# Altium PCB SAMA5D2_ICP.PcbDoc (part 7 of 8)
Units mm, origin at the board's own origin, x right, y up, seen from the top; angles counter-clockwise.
Board outline 150 x 100 mm, 6 copper layers (L1 - TOP, L2 - GND, L3 - SIG, L4 - SIG, L5 - VCC, L6 - BOT), stack 1.512 mm thick; 708 components, 597 nets, 2710 pads, 1437 vias.
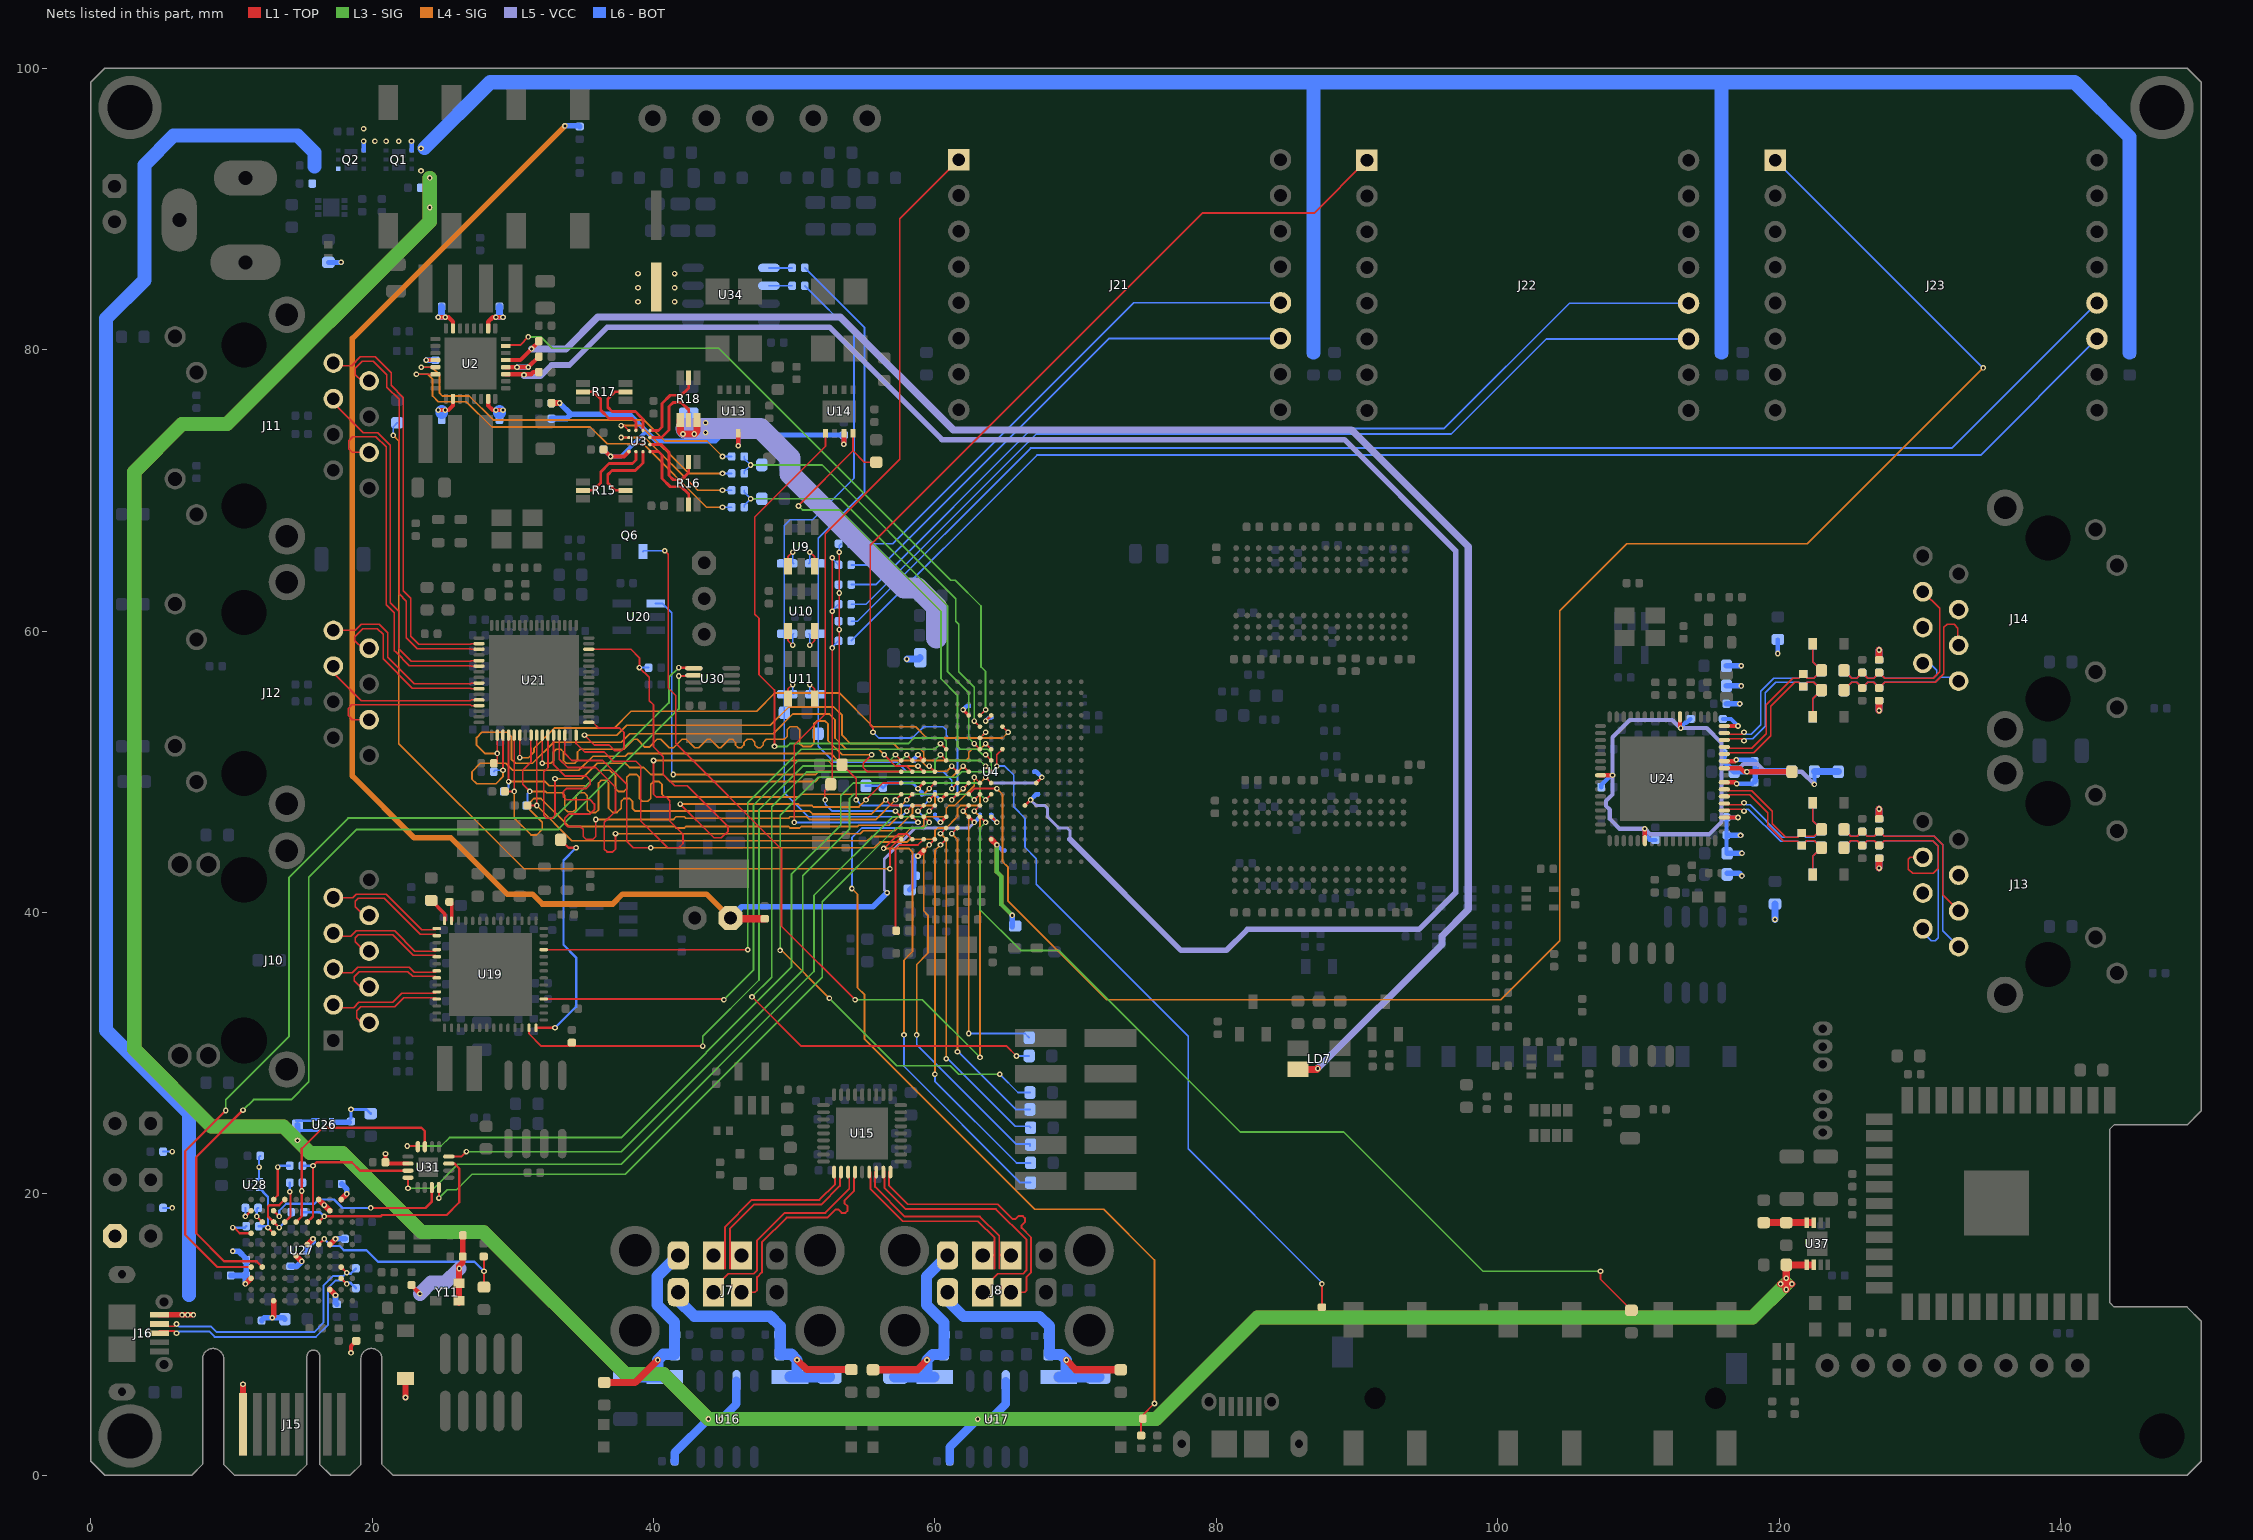
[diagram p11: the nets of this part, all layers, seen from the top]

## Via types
v1: diameter 0.4, hole 0.2, L1 - TOP to L6 - BOT, tented both sides, 1312 vias
v2: diameter 0.55, hole 0.3, L1 - TOP to L6 - BOT, 84 vias
v3: diameter 0.4, hole 0.2, L1 - TOP to L6 - BOT, tented top, 25 vias
v4: diameter 0.55, hole 0.3, L1 - TOP to L6 - BOT, tented bottom, 16 vias

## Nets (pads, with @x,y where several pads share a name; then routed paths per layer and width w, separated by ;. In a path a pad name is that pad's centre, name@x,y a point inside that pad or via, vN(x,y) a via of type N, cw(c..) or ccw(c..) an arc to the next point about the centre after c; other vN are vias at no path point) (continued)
PC22: R131.1 U4.H2 U19.27 | length 44.3
  L1 - TOP w0.125: U19.27@31.15,31.8 31.15,31.381 32.031,30.5 v1(43.5,30.5) ; v1(58,51.2) U4.H2@58.4,50.8
  L3 - SIG w0.125: v1(43.5,30.5) 43.5,31.2 47.5,35.2 47.5,47.3 50.6,50.4 57.2,50.4 v1(58,51.2)
PC23: U4.G5 U19.39 | length 41
  L1 - TOP w0.125: U19.39@32.2,37.35 v1(46.7,37.35) ; v1(60.4,52) U4.G5@60.8,51.6
  L3 - SIG w0.125: v1(46.7,37.35) 46.7,47.8 50.5,51.6 60,51.6 v1(60.4,52)
PC24: U4.H1 U19.32 | length 39.6
  L1 - TOP w0.125: U19.32@32.2,33.85 44.95,33.85 v1(45,33.8) ; v1(57.2,51.2) U4.H1@57.6,50.8
  L3 - SIG w0.125: v1(45,33.8) 47.1,35.9 47.1,47.6 50.3,50.8 56.8,50.8 v1(57.2,51.2)
PC25: R235.1 U4.H5 | length 50
  L1 - TOP w0.125: v1(47,34) 50.5,30.5 65.1,30.5 v1(65.8,29.8) ; v1(60.4,51.2) U4.H5@60.8,50.8
  L3 - SIG w0.125: v1(47,34) 48.4,35.4 48.4,47.5 50.875,49.975 59.775,49.975 60,50.2 60,50.8 v1(60.4,51.2)
  L6 - BOT w0.125: v1(65.8,29.8) R235.1@66.7,29.8
PC26: U4.J9 U14.1 | length 42.2
  L1 - TOP w0.125: v1(48.6,51.8) 48.6,55.8 47.5,56.9 47.5,60.9 47.2,61.2 47.2,68.1 52.225,73.125 U14.1@52.225,74.05 ; v1(63.6,50.4) U4.J9@64,50
  L3 - SIG w0.125: v1(48.6,51.8) 49.5,51.8 49.7,52 58.1,52 58.5,52.4 60.575,52.4 60.8,52.175 60.8,51.075 60.775,51.05 61.025,50.8 63.2,50.8 v1(63.6,50.4)
PC27: C125.2 U4.H9 U14.4 | length 34.9
  L1 - TOP w0.125: v1@50.28,68.905 54.175,72.8 ; U14.4@54.175,74.05 54.175,72.8 ; C125.2@55.831,71.994 54.981,71.994 54.175,72.8 ; v1(63.6,51.2) U4.H9@64,50.8
  L3 - SIG w0.125: v1(50.3,68.885) 50.309,68.885 50.594,68.6 53.231,68.6 60.435,61.396 60.435,56.6 61.6,55.435 61.6,51.8 61.8,51.6 63,51.6 63.4,51.2 v1(63.6,51.2)
PC28: R47.1 R60.1 R61.1 U4.E8 | length 30.7
  L1 - TOP w0.125: v1(62.8,53.6) U4.E8@63.2,53.2
  L3 - SIG w0.125: v1(46.9,71.8) 51.98,71.8 61.478,62.302 61.478,60.694 61.7,60.472 61.7,57.1 62.8,56 v1(62.8,53.6)
  L6 - BOT w0.125: R61.1@46.45,71.2 46.45,71.35 v1(46.9,71.8) ; R60.1@46.45,72.4 46.45,72.25 v1(46.9,71.8) ; R47.1@47.7,71.8 v1(46.9,71.8)
PC28_MCP16502: R60.2 U2.5 | length 26.4
  L1 - TOP w0.125: v1(23.5,78.75) U2.5@24.5,78.75
  L4 - SIG w0.125: v1(23.5,78.75) 24.25,78.75 24.8,78.2 24.8,76.9 25,76.7 26.9,76.7 28.6,75 39.3,75 40.8,73.5 43.8,73.5 v1(44.9,72.4)
  L6 - BOT w0.125: v1(44.9,72.4) R60.2@45.55,72.4
PC28_PAC1934: R61.2 U3.D4 | length 10
  L1 - TOP w0.125: v1(37.7,74.6) 37.9,74.6 U3.D4@38.25,74.25
  L4 - SIG w0.125: v1(37.7,74.6) 39.1,74.6 42.5,71.2 v1(44.9,71.2)
  L6 - BOT w0.125: v1(44.9,71.2) R61.2@45.55,71.2
PC29: R44.1 R62.1 R63.1 U4.G8 | length 30.7
  L1 - TOP w0.125: v1(62.8,52) U4.G8@63.2,51.6
  L3 - SIG w0.125: v1(46.9,69.4) 53.28,69.4 60.9,61.78 60.9,57.1 62.4,55.6 62.4,52.4 v1(62.8,52)
  L6 - BOT w0.125: R62.1@46.45,68.8 46.45,68.95 v1(46.9,69.4) ; R63.1@46.45,70 46.45,69.85 v1(46.9,69.4) ; R44.1@47.7,69.4 v1(46.9,69.4)
PC29_MCP16502: R62.2 U2.6 | length 28.4
  L1 - TOP w0.125: v1(23.15,78.25) U2.6@24.5,78.25
  L4 - SIG w0.125: v1(23.15,78.25) 23.95,78.25 24.3,77.9 24.3,76.7 24.7,76.3 26.7,76.3 28.5,74.5 35.5,74.5 36.7,73.3 39.266,73.3 43.766,68.8 v1(44.9,68.8)
  L6 - BOT w0.125: v1(44.9,68.8) R62.2@45.55,68.8
PC29_PAC1934: R63.2 U3.C4 | length 10
  L1 - TOP w0.125: v1(37.7,73.75) U3.C4@38.25,73.75
  L4 - SIG w0.125: v1(37.7,73.75) 39.381,73.75 43.131,70 v1(44.9,70)
  L6 - BOT w0.125: v1(44.9,70) R63.2@45.55,70
PC30: R234.2 U4.F8 | length 51.8
  L1 - TOP w0.125: U4.F8@63.2,52.4 v1(63.6,52.8)
  L3 - SIG w0.125: v1(49,37.3) 49,46.9 51.7,49.6 61.5,49.6 61.9,50 63.8,50 64,50.2 64,51.35 63.75,51.6 63.4,51.6 63.2,51.8 63.2,52.4 v1(63.6,52.8) ; v1(52.5,33.9) 57.3,29.1 61.1,29.1 61.7,28.5 v1(64.6,28.5)
  L4 - SIG w0.125: v1(49,37.3) 49.1,37.3 v1(52.5,33.9)
  L6 - BOT w0.125: v1(64.6,28.5) 65.9,27.2 R234.2@66.75,27.2
PC31: U2.23 U4.D8 | length 50
  L1 - TOP w0.125: U2.23@29.5,80.25 29.567,80.317 30.517,80.317 v1(31.1,80.9) ; U4.D8@63.2,54 v1(63.6,54.4)
  L3 - SIG w0.125: v1(31.1,80.9) 32,80.9 32.8,80.1 44.625,80.1 61.113,63.612 61.438,63.612 63.275,61.775 63.275,57.45 63.6,57.125 v1(63.6,54.4)
PD0: R254.1 U4.G10 | length 49.7
  L1 - TOP w0.125: v1(64.4,50.4) 64.4,51.2 U4.G10@64.8,51.6 ; R254.1@87.5,11.95 v1(87.5,13.6)
  L6 - BOT w0.125: v1(64.4,50.4) 64.966,50.4 65.6,49.766 65.6,47.5 66.4,46.7 66.4,44.625 67.2,43.825 67.2,42 78,31.2 78,23.2 87.5,13.7 v1(87.5,13.6)
PD1: U4.E10 U21.22 | length 40.4
  L1 - TOP w0.125: v1(30.5,51) U21.22@30.5,52.6 ; U4.E10@64.8,53.2 v1(65.2,52.8)
  L4 - SIG w0.125: v1(30.5,51) 31.117,51 31.5,51.383 31.5,51.65 32.95,53.1 37.2,53.1 38.4,54.3 47.334,54.3 48.634,55.6 53.2,55.6 55.6,53.2 58.625,53.2 59.425,52.4 64.8,52.4 v1(65.2,52.8)
PD2: U4.G9 U21.33 | length 40.4
  L1 - TOP w0.125: v1(35.1,52.6) 35.8,51.9 36.85,51.9 37.25,51.5 37.7,51.5 37.9,51.7 37.9,52.8 37.6,53.1 36.1,53.1 35.7,53.5 U21.33@35.4,53.5 ; v1(63.6,52) U4.G9@64,51.6
  L4 - SIG w0.125: v1(35.1,52.6) 37.4,52.6 38.1,53.3 48.3,53.3 49.6,54.6 52.8,54.6 53.4,54 53.4,52.6 54,52 57.075,52 57.475,51.6 58.975,51.6 59.2,51.375 59.2,51.025 59.425,50.8 62.2,50.8 62.4,51 62.4,51.375 62.625,51.6 63.2,51.6 v1(63.6,52)
PD3: R177.1 U4.K1 U21.46 | length 41
  L1 - TOP w0.125: U21.46@35.4,58.7 38.4,58.7 39,58.1 v1(39,57.4) 39.7,56.7 39.7,55.048 40,54.748 40,51.775 40.7,51.075 40.7,49.8 41.5,49 42.4,49 45.3,46.1 45.3,45.775 44.825,45.3 44.3,45.3 v1(41.9,47.7) ; v1(55.1,48) 56.3,49.2 U4.K1@57.6,49.2
  L4 - SIG w0.125: v1(41.9,47.7) 50.3,47.7 50.4,47.6 51.266,47.6 51.366,47.5 54.6,47.5 v1(55.1,48)
  L6 - BOT w0.125: v1(39,57.4) R177.1@39.65,57.4
PD4: U4.J6 U20.1 | length 33.6
  L1 - TOP w0.125: v1(61.2,50.4) U4.J6@61.6,50
  L4 - SIG w0.125: v1(41.4,49.8) 51.52,49.8 51.75,50.03 60.83,50.03 v1(61.2,50.4)
  L6 - BOT w0.125: U20.1@40.15,61.95 40.65,61.95 41.3,61.3 41.3,49.9 v1(41.4,49.8)
PD5: R157.1 U4.J4 U21.19 | length 41.1
  L1 - TOP w0.125: v1(29.3,50.1) U21.19@29.3,52.6 ; v1(59.6,50.4) U4.J4@60,50
  L4 - SIG w0.125: v1(29.3,50.1) 29.3,49.64 28.81,49.15 27.425,49.15 27.1,49.475 27.1,50 27.7,50.6 29.5,50.6 30,50.1 34.7,50.1 35.7,51.1 38,51.1 38.2,51.3 52.6,51.3 53.1,50.8 59,50.8 59.4,50.4 v1(59.6,50.4)
  L6 - BOT w0.125: R157.1@28.65,50 28.75,50.1 v1(29.3,50.1)
PD6: R266.1 U4.J2 U21.18 | length 41.2
  L1 - TOP w0.125: R266.1@28.9,50.6 v1(28.9,51.3) U21.18@28.9,52.6 ; v1(56.4,51.2) 57.2,50.4 58,50.4 U4.J2@58.4,50
  L4 - SIG w0.125: v1(28.9,51.3) 28,51.3 27.425,51.875 27.425,52.425 27.8,52.8 29.6,52.8 29.9,52.5 29.9,50.9 30.2,50.6 31.4,50.6 32.9,52.1 37.7,52.1 38.3,52.7 48.5,52.7 49.9,54.1 52.5,54.1 52.9,53.7 52.9,52.4 53.7,51.6 56,51.6 v1(56.4,51.2)
PD7: U4.J7 U21.27 | length 40.4
  L1 - TOP w0.125: U21.27@32.5,52.6 32.5,50.3 32.2,50 32.2,46.9 32.4,46.7 32.8,46.7 33,46.9 v1(33,49.5) ; v1(62,50.4) U4.J7@62.4,50
  L4 - SIG w0.125: v1(33,49.5) 34.9,49.5 36,50.6 38,50.6 38.3,50.3 39.3,50.3 39.8,49.8 40.7,49.8 41.2,49.3 51.5,49.3 51.8,49.6 61.2,49.6 v1(62,50.4)
PD8: U4.J1 U21.26 | length 40.4
  L1 - TOP w0.125: v1(32.1,50.6) U21.26@32.1,52.6 ; v1(55.5,51.2) 54.9,50.6 54.9,50.3 55.2,50 U4.J1@57.6,50
  L4 - SIG w0.125: v1(32.1,50.6) 32.7,50.6 32.9,50.8 32.9,51.4 33.1,51.6 33.4,51.6 33.6,51.4 33.6,50.8 33.8,50.6 34.4,50.6 34.6,50.8 34.6,51.4 34.8,51.6 37.9,51.6 38.6,52.3 38.834,52.3 39.384,51.75 39.7,51.75 40.25,52.3 40.525,52.3 41.125,51.7 41.425,51.7 42.025,52.3 42.325,52.3 42.925,51.7 43.225,51.7 43.825,52.3 44.025,52.3 44.625,51.7 44.78,51.7 45.38,52.3 45.625,52.3 45.825,52.1 45.825,51.9 46.025,51.7 46.225,51.7 46.425,51.9 46.425,52.075 46.65,52.3 47,52.3 47.2,52.1 47.2,51.9 47.4,51.7 47.6,51.7 47.8,51.9 47.8,52.075 48.025,52.3 49.3,52.3 49.5,52.5 49.5,53 49.7,53.2 50.2,53.2 50.4,53 50.4,52 50.6,51.8 51.2,51.8 51.4,52 51.4,53.4 51.6,53.6 52.2,53.6 52.4,53.4 52.4,52.2 53.4,51.2 v1(55.5,51.2)
PD9: U4.K9 U21.30 | length 40.4
  L1 - TOP w0.125: U21.30@33.7,52.6 33.7,51.3 34.2,50.8 36.4,50.8 38.1,49.1 38.1,45.05 38.55,44.6 v1(39.8,44.6) ; v1(63.6,49.6) U4.K9@64,49.2
  L4 - SIG w0.125: v1(39.8,44.6) 55.7,44.6 56.1,45 58,45 58.2,45.2 59.8,45.2 60,45.4 60,45.8 60.2,46 60.8,46 61.6,46.8 61.6,47.376 61.824,47.6 63.1,47.6 63.2,47.7 63.2,49.2 v1(63.6,49.6)
PD10: U4.J3 U21.32 | length 40.4
  L1 - TOP w0.125: U21.32@34.5,52.6 34.5,52.007 35.107,51.4 36.5,51.4 37.15,50.75 38.757,50.75 39.1,50.407 39.1,46.5 41,44.6 41.8,44.6 42.1,44.9 42.1,45.56 41.16,46.5 41.16,47.94 40.9,48.2 40.2,48.2 40,48.4 v1(40,50.8) ; v1(58.8,50.4) U4.J3@59.2,50
  L4 - SIG w0.125: v1(40,50.8) 52.4,50.8 52.8,50.4 v1(58.8,50.4)
PD11: R259.1 U4.M1 U21.24 | length 41.5
  L1 - TOP w0.125: v1(31.2,48.6) 30.7,49.1 30.7,50.1 31.3,50.7 31.3,51.666 31.275,51.691 31.275,52.575 U21.24@31.3,52.6 ; v1(56.5,48) 56.9,47.6 U4.M1@57.6,47.6
  L4 - SIG w0.125: v1(31.2,48.6) 32.3,48.6 32.4,48.5 33.5,48.5 33.7,48.3 33.7,47.35 33.9,47.15 34.3,47.15 34.5,47.35 34.5,48.3 34.7,48.5 35.1,48.5 35.3,48.3 35.3,47.3 35.5,47.1 35.9,47.1 36.1,47.3 36.1,49.2 36.3,49.4 36.6,49.4 36.8,49.2 36.8,47.4 37.1,47.1 37.4,47.1 37.7,47.4 37.7,47.9 37.9,48.1 38.3,48.1 38.5,47.9 38.5,47.4 38.7,47.2 51.1,47.2 51.3,47 55.5,47 v1(56.5,48)
  L6 - BOT w0.125: R259.1@31.05,47.6 31.05,48.45 v1(31.2,48.6)
PD12: R267.1 U4.K8 U21.25 | length 41
  L1 - TOP w0.125: R267.1@31.1,47.6 v1(31.7,47.6) U21.25@31.7,52.6 ; v1(62.8,49.6) U4.K8@63.2,49.2
  L4 - SIG w0.125: v1(31.7,47.6) 34.2,45.1 55.2,45.1 55.5,45.4 57.7,45.4 58.3,46 59,46 59.2,46.2 59.2,46.6 59.4,46.8 60.7,46.8 60.8,46.9 60.8,47.4 61,47.6 61.4,47.6 62.8,49 v1(62.8,49.6)
PD13: R155.1 U4.L2 U21.21 | length 41.1
  L1 - TOP w0.125: R155.1@29.45,48.6 v1(30.1,48.6) U21.21@30.1,52.6 ; v1(58,48) U4.L2@58.4,48.4
  L4 - SIG w0.125: v1(30.1,48.6) 30.1,46.7 31.3,45.5 31.7,45.5 32.1,45.9 32.1,46.4 31.2,47.3 31.2,47.8 31.5,48.1 32,48.1 34,46.1 41.5,46.1 41.6,46 42.2,46 42.3,46.1 49.6,46.1 49.7,46 50.4,46 50.5,46.1 54.5,46.1 54.6,46.2 56.766,46.2 57.6,47.034 57.6,47.6 v1(58,48)
PD14: R156.2 U4.K4 U21.20 | length 41.2
  L1 - TOP w0.125: v1(29.7,49.3) U21.20@29.7,52.6 ; v1(59.6,48.8) U4.K4@60,49.2
  L4 - SIG w0.125: v1(29.7,49.3) 32.3,49.3 32.6,49 35.2,49 36.3,50.1 36.9,50.1 37.3,49.7 37.3,48.8 37.5,48.6 37.9,48.6 38.1,48.8 38.1,49.6 38.3,49.8 38.8,49.8 39,49.6 39,48.1 39.2,47.9 39.6,47.9 39.8,48.1 39.8,49.1 40,49.3 40.4,49.3 40.6,49.1 40.6,48.4 40.8,48.2 50.3,48.2 50.5,48.4 59.2,48.4 v1(59.6,48.8)
  L6 - BOT w0.125: R156.2@29.45,48.6 29.7,48.85 v1(29.7,49.3)
PD15: U4.K7 U21.29 | length 40.4
  L1 - TOP w0.125: U21.29@33.3,52.6 33.3,50.9 33.9,50.3 35.9,50.3 37.3,48.9 37.3,47.2 36.5,46.4 36.5,44.5 36.7,44.3 37.1,44.3 37.3,44.5 v1(37.3,45.6) ; v1(62,48.8) U4.K7@62.4,49.2
  L4 - SIG w0.125: v1(37.3,45.6) 54.7,45.6 54.9,45.8 57.166,45.8 58.4,47.034 58.4,47.4 58.6,47.6 59.9,47.6 60,47.7 60,48.2 60.2,48.4 61.6,48.4 v1(62,48.8)
PD16: U4.L1 U21.28 | length 40.4
  L1 - TOP w0.125: U21.28@32.9,52.6 32.9,50.5 33.7,49.7 35.2,49.7 35.5,49.4 35.5,49.1 35.2,48.8 33.8,48.8 33.6,48.6 33.6,48.2 33.8,48 35.5,48 35.8,47.7 35.8,47.3 35.5,47 34,47 33.7,46.7 33.7,46.3 33.9,46.1 34.8,46.1 35,45.9 35,45.4 35.2,45.2 35.7,45.2 35.9,45.4 v1(35.9,46.6) ; v1(57.2,48) U4.L1@57.6,48.4
  L4 - SIG w0.125: v1(35.9,46.6) 41.4,46.6 41.6,46.8 42.2,46.8 42.3,46.7 49.6,46.7 49.7,46.8 50.9,46.8 51.1,46.6 55.8,46.6 v1(57.2,48)
PD19: R45.1 R48.1 R49.1 R50.1 R269.1 U4.K6 | length 48.8
  L1 - TOP w0.125: v1(61.2,48.8) U4.K6@61.6,49.2
  L6 - BOT w0.125: R269.1@50.75,85.805 55,81.555 55,69.9 51.7,66.6 R45.1@51.7,52.7 51.7,51.8 52.8,50.7 57.3,50.7 58,50 60.6,50 61.2,49.4 v1(61.2,48.8)
PD19_ECC608: R269.2 U34.5 | length 1.7
  L6 - BOT w0.125: U34.5@48.2,85.805 R269.2@49.85,85.805
PD19_EEPROM1: R48.2 U9.3 | length 2
  L1 - TOP w0.125: v1(51.1,65.6) 51.125,65.6 51.45,65.275 U9.3@51.45,64.6
  L6 - BOT w0.125: R48.2@51.05,64.8 51.1,64.85 v1(51.1,65.6)
PD19_EEPROM2: R49.2 U10.3 | length 2
  L1 - TOP w0.125: v1(51.1,59) 51.125,59 51.45,59.325 U10.3@51.45,60
  L6 - BOT w0.125: R49.2@51.05,59.8 51.1,59.75 v1(51.1,59)
PD19_EEPROM3: R50.2 U11.3 | length 1.9
  L1 - TOP w0.125: v1(51.1,56.2) 51.125,56.2 51.45,55.875 U11.3@51.45,55.2
  L6 - BOT w0.125: R50.2@51.05,55.5 51.1,55.55 v1(51.1,56.2)
PD20: R42.1 R51.1 R52.1 R53.1 R270.1 U4.M2 | length 50.6
  L1 - TOP w0.125: v1(58,47.2) U4.M2@58.4,47.6
  L6 - BOT w0.125: R270.1@50.75,84.535 54.25,81.035 54.25,70.85 51.3,67.9 49.7,67.9 49.3,67.5 49.3,48.5 51,46.8 57.6,46.8 v1(58,47.2)
PD20_ECC608: R270.2 U34.6 | length 1.7
  L6 - BOT w0.125: U34.6@48.2,84.535 R270.2@49.85,84.535
PD20_EEPROM1: R51.2 U9.1 | length 2
  L1 - TOP w0.125: U9.1@49.55,64.6 49.55,65.275 49.875,65.6 v1(49.9,65.6)
  L6 - BOT w0.125: v1(49.9,65.6) 49.9,64.85 R51.2@49.95,64.8
PD20_EEPROM2: R52.2 U10.1 | length 2
  L1 - TOP w0.125: U10.1@49.55,60 49.55,59.325 49.875,59 v1(49.9,59)
  L6 - BOT w0.125: v1(49.9,59) 49.9,59.75 R52.2@49.95,59.8
PD20_EEPROM3: R53.2 U11.1 | length 1.9
  L1 - TOP w0.125: U11.1@49.55,55.2 49.55,55.875 49.875,56.2 v1(49.9,56.2)
  L6 - BOT w0.125: v1(49.9,56.2) 49.9,55.55 R53.2@49.95,55.5
PD21: R46.1 R54.1 R55.1 R56.1 U4.N1 | length 25.6
  L1 - TOP w0.125: v1(52.2,48) 52.165,48.035 52.165,48.665 R46.1@52.6,49.1 52.7,49.2 v1(52.7,58.8) v1(52.7,61.4) v1(52.7,65.2) ; v1(57.2,47.2) U4.N1@57.6,46.8
  L6 - BOT w0.125: v1(52.2,48) 52.2,47.7 52.7,47.2 v1(57.2,47.2) ; v1(52.7,58.8) 52.7,58.85 R56.1@53.15,59.3 ; v1(52.7,61.4) 52.7,61.45 R55.1@53.15,61.9 ; v1(52.7,65.2) 52.7,65.15 R54.1@53.15,64.7
PD21_MKBUS1: J21.11 R54.2 | length 37.2
  L6 - BOT w0.125: R54.2@54.05,64.7 56.3,64.7 72.395,80.795 J21.11@84.56,80.795
PD21_MKBUS2: J22.11 R55.2 | length 67.3
  L6 - BOT w0.125: R55.2@54.05,61.9 55.1,61.9 67.2,74 96.7,74 103.455,80.755 J22.11@113.56,80.755
PD21_MKBUS3: J23.11 R56.2 | length 97.4
  L6 - BOT w0.125: R56.2@54.05,59.3 67.25,72.5 134.315,72.5 J23.11@142.58,80.765
PD22: R43.1 R57.1 R58.1 R59.1 U4.L4 | length 26.1
  L1 - TOP w0.125: v1(53.2,65.6) v1(53.2,62.7) v1(53.2,60.1) 53.2,50.7 R43.1@53.4,50.5 54.4,49.5 v1(54.4,48) ; v1(59.6,48) U4.L4@60,48.4
  L6 - BOT w0.125: R59.1@53.15,60.7 53.2,60.65 v1(53.2,60.1) ; R58.1@53.15,63.3 53.2,63.25 v1(53.2,62.7) ; v1(53.2,65.6) 53.2,66.05 R57.1@53.35,66.2 ; v1(54.4,48) 54.8,47.6 59.2,47.6 v1(59.6,48)
PD22_MKBUS1: J21.12 R57.2 | length 37.6
  L6 - BOT w0.125: R57.2@54.05,66.2 57,66.2 74.135,83.335 J21.12@84.56,83.335
PD22_MKBUS2: J22.12 R58.2 | length 67.8
  L6 - BOT w0.125: R58.2@54.05,63.3 55.8,63.3 66.9,74.4 96.2,74.4 105.095,83.295 J22.12@113.56,83.295
PD22_MKBUS3: J23.12 R59.2 | length 97.9
  L6 - BOT w0.125: R59.2@54.05,60.7 54.5,60.7 66.8,73 132.275,73 J23.12@142.58,83.305
PD23: R129.2 R130.1 U4.M3 | length 61.8
  L1 - TOP w0.125: v1(58.8,47.2) U4.M3@59.2,47.6 ; R129.2@74.652,2.824 74.652,3.899 R130.1@74.777,4.024 74.777,4.277 v1(75.6,5.1)
  L4 - SIG w0.125: v1(54.1,41.7) 54.5,41.3 54.5,34.64 55,34.14 55,31 67.1,18.9 72,18.9 75.6,15.3 v1(75.6,5.1)
  L6 - BOT w0.125: v1(54.1,41.7) 54.1,45.3 54.8,46 59,46 59.2,46.2 59.2,46.8 v1(58.8,47.2)
PD24: J23.1 U4.L7 | length 136
  L1 - TOP w0.125: U4.L7@62.4,48.4 62.8,48.8 v1(64.4,48.8)
  L4 - SIG w0.125: v1(64.4,48.8) 64.8,48.4 64.8,43.6 65.202,43.198 65.202,40.798 72.2,33.8 100.2,33.8 104.4,38 104.4,61.434 104.966,62 109.166,66.2 119.6,66.2 122,66.2 v1(134.5,78.7)
  L6 - BOT w0.125: J23.1@119.72,93.465 v1@134.542,78.643
PD25: J22.1 U4.L6 | length 72.1
  L1 - TOP w0.125: v1(55.6,52.8) 55.6,53.1 55.4,53.3 55.4,66.1 79,89.7 86.945,89.7 J22.1@90.7,93.455 ; v1(61.2,48) U4.L6@61.6,48.4
  L6 - BOT w0.125: v1(55.6,52.8) 56,52.4 58.4,52.4 59.2,53.2 60.576,53.2 60.8,52.976 60.8,52.6 61,52.4 61.4,52.4 61.6,52.2 61.6,48.4 v1(61.2,48)
PD26: J21.1 U4.N2 | length 61.3
  L1 - TOP w0.125: v1(50,46.4) 50,51.9 52.2,54.1 52.2,66.9 57.5,72.2 57.5,89.295 J21.1@61.7,93.495 ; U4.N2@58.4,46.8 v1(58.8,46.4)
  L6 - BOT w0.125: v1(50,46.4) v1(58.8,46.4)
PD27: U4.L8 U31.8 | length 53.9
  L1 - TOP w0.125: U31.8@25.45,22.65 26.35,22.65 v1(26.7,23) ; v1(62.8,48) U4.L8@63.2,48.4
  L3 - SIG w0.125: v1(26.7,23) 37.7,23 50.6,35.9 50.6,42.6 53.934,45.934 53.934,48.1 54.234,48.4 62.4,48.4 v1(62.8,48)
PD28: U4.M4 U31.16 | length 52.6
  L1 - TOP w0.125: v1(22.55,20.4) U31.16@22.55,21.15 ; v1(59.6,47.2) U4.M4@60,47.6
  L3 - SIG w0.125: v1(22.55,20.4) 24.4,20.4 26.1,22.1 37.7,22.1 51.4,35.8 51.4,41.2 57,46.8 59.2,46.8 v1(59.6,47.2)
PD29: U4.N3 U31.4 | length 50.4
  L1 - TOP w0.125: v1(24.75,19.7) U31.4@24.75,20.45 ; U4.N3@59.2,46.8 v1(59.6,46.4)
  L3 - SIG w0.125: v1(24.75,19.7) 25.35,20.3 26,20.3 27.1,21.4 38,21.4 52,35.4 52,40.766 57.234,46 59.2,46 v1(59.6,46.4)
PD30: U4.L9 U31.12 | length 59.1
  L1 - TOP w0.125: v1(22.5,23.4) 23.2,23.4 U31.12@23.25,23.35 ; v1(63.6,48) U4.L9@64,48.4
  L3 - SIG w0.125: v1(22.5,23.4) 24.9,23.4 25.5,24 37.7,24 49.8,36.1 49.8,42.7 53.3,46.2 53.3,48.3 54.2,49.2 63,49.2 63.2,49 63.2,48.4 v1(63.6,48)
PD31: R228.2 U4.M7 | length 21
  L1 - TOP w0.125: v1(62,47.2) U4.M7@62.4,47.6
  L4 - SIG w0.125: v1(62,47.2) 62.4,46.8 v1(62.4,31.4)
  L6 - BOT w0.125: v1(62.4,31.4) 66.4,31.4 R228.2@66.7,31.1
PIOBU1: R255.2 U4.N8 | length 65.4
  L1 - TOP w0.125: U4.N8@63.2,46.8 v1(63.6,46.4) ; v1(107.3,14.5) 107.3,13.925 R255.2@109.5,11.725
  L3 - SIG w0.125: v1(63.6,46.4) 63.2,46 63.2,40.2 66.1,37.3 68.8,37.3 81.7,24.4 89.05,24.4 98.95,14.5 v1(107.3,14.5)
PIOBU2: R224.1 U4.R2 | length 32.7
  L1 - TOP w0.125: v1(56.35,44.55) 56.385,44.55 57.4,45.565 58.035,45.565 U4.R2@58.4,45.2
  L4 - SIG w0.125: v1(56.35,44.55) 58.15,44.55 58.4,44.3 58.4,37.2 57.8,36.6 v1(57.8,31.3)
  L6 - BOT w0.125: v1(57.8,31.3) 57.8,29.068 66.068,20.8 R224.1@66.8,20.8
PIOBU3: R232.2 U4.R5 | length 26.7
  L1 - TOP w0.125: v1(60.4,44.8) U4.R5@60.8,45.2
  L4 - SIG w0.125: v1(60,28.5) 60,44.4 v1(60.4,44.8)
  L6 - BOT w0.125: v1(60,28.5) 60,28 65.8,22.2 R232.2@66.8,22.2
PIOBU4: R225.1 U4.R4 | length 26.5
  L1 - TOP w0.125: v1(59.6,44.8) U4.R4@60,45.2
  L4 - SIG w0.125: v1(58.7,31.3) 58.7,36.3 59.5,37.1 59.5,39.8 59.2,40.1 59.2,44.4 v1(59.6,44.8)
  L6 - BOT w0.125: v1(58.7,31.3) 58.7,30.6 65.75,23.55 66.75,23.55 R225.1@66.75,23.4
PIOBU5: R233.2 U4.P5 | length 24.8
  L1 - TOP w0.125: v1(60.4,45.6) U4.P5@60.8,46
  L4 - SIG w0.125: v1(60.4,45.6) 60.8,45.2 v1(60.8,29.6)
  L6 - BOT w0.125: v1(60.8,29.6) 60.9,29.6 65.7,24.8 66.7,24.8 R233.2@66.8,24.7
PIOBU6: R226.1 U4.P6 | length 23.1
  L1 - TOP w0.125: v1(61.2,45.6) U4.P6@61.6,46
  L4 - SIG w0.125: v1(61.2,45.6) 61.6,45.2 v1(61.6,30.1)
  L6 - BOT w0.125: v1(61.6,30.1) 61.65,30.1 65.75,26 R226.1@66.75,26
PIOBU7: Q6.1 U4.M8 | length 67.9
  L1 - TOP w0.125: v1(40.8,65.7) 41.05,65.45 41.05,55.95 41.58,55.42 41.58,52.02 49.1,44.5 49.1,39.03 v1(54.33,33.8) ; v1(62.8,47.2) U4.M8@63.2,47.6
  L3 - SIG w0.125: v1(54.33,33.8) 59.1,33.8 v1(63.2,29.7)
  L4 - SIG w0.125: v1(62.8,47.2) 63.2,46.8 v1(63.2,29.7)
  L6 - BOT w0.125: Q6.1@39.25,65.65 39.3,65.7 v1(40.8,65.7) ; v1(63.2,29.7) v1@63.25,29.7
PIOUB0: R185.1 U4.R3 | length 8.1
  L1 - TOP w0.125: R185.1@57.2,38.7 57.2,44.516 57.484,44.8 58.8,44.8 U4.R3@59.2,45.2
PWR1: C148.2 C282.2 C284.2 FB11.2 J7.1 R127.1 | length 17.9
  L1 - TOP w0.5: R127.1@36.5,6.6 38.7,6.6 v1(40.3,8.2)
  L6 - BOT w0.8: C284.2@38,7 C282.2@40.8,7 ; C282.2@40.3,7.1 v1(40.3,8.2) 40.7,8.6 FB11.2@41.5,8.6 41.5,10.875 40.265,12.11 40.265,14.145 J7.1@41.76,15.64
PWR2: C153.2 C295.2 C297.2 FB10.2 J7.5 R128.1 | length 20.1
  L1 - TOP w0.5: v1(50.2,8.2) 50.89,7.51 R128.1@54.06,7.51
  L6 - BOT w0.8: J7.5@41.76,13.01 41.76,12.44 42.9,11.3 48.3,11.3 49,10.6 FB10.2@49,8.6 49.8,8.6 v1(50.2,8.2) C295.2@50.2,7 ; C295.2@49.7,7 C295.2@50.2,7 ; C297.2@52.5,7 C295.2@50.2,7
PWR3: C149.2 C283.2 C285.2 FB13.2 J8.1 R125.1 | length 17.6
  L1 - TOP w0.5: R125.1@55.6,7.5 58.75,7.5 v1(59.44,8.19)
  L6 - BOT w0.8: C285.2@57.14,6.99 C283.2@59.94,6.99 ; C283.2@59.44,7.025 v1(59.44,8.19) 59.84,8.59 60.64,8.59 60.64,9.99 60.64,10.865 59.405,12.1 59.405,14.135 J8.1@60.9,15.63
PWR4: C154.2 C296.2 C298.2 FB12.2 J8.5 R126.1 | length 20.1
  L1 - TOP w0.5: v1(69.34,8.19) 70,7.53 70,7.5 R126.1@73.2,7.5
  L6 - BOT w0.8: J8.5@60.9,13 60.9,12.43 62.04,11.29 67.44,11.29 68.14,10.59 68.14,8.59 68.94,8.59 v1(69.34,8.19) C296.2@69.34,6.99 ; C296.2@68.84,6.99 C296.2@69.34,6.99 ; C298.2@71.64,6.99 C296.2@69.34,6.99
REF_FILT: C159.2 U19.56 | length 1.8
  L1 - TOP w0.25: C159.2@24.2,40.855 25.15,39.905 U19.56@25.15,39.4
REF_REXT: R139.2 U19.55 | length 1.5
  L1 - TOP w0.25: R139.2@25.5,40.805 25.65,40.655 U19.55@25.65,39.4
RTCKIN: R208.2 R209.2 U27.F4 | length 15.1
  L1 - TOP w0.165: U27.F4@16.2,16.4 v1(16.6,16.8) ; R208.2@27.925,15.55 27.95,15.525 v1(27.95,14.5) R209.2@27.95,13.375
  L6 - BOT w0.165: v1(16.6,16.8) 17.1,16.3 17.698,16.3 17.998,16 19.6,16 20.425,15.175 27.275,15.175 v1(27.95,14.5)
RX1_N: J11.6 U21.6 | length 26.4
  L1 - TOP w0.102: J11.6@19.79,72.695 18.605,72.695 18.35,72.95 18.35,73.525 18.625,73.8 20.275,73.8 20.995,73.08 20.995,61.874 21.583,61.286 21.583,58.611 21.672,58.522 22.646,57.548 27.002,57.548 27.049,57.5 U21.6@27.6,57.5
RX1_P: J11.3 U21.5 | length 26.4
  L1 - TOP w0.102: J11.3@17.25,76.505 17.25,76.23 19.375,74.105 20.401,74.105 20.491,74.016 21.3,73.206 21.3,62 21.888,61.413 21.888,58.737 22.773,57.852 27.002,57.852 27.049,57.9 U21.5@27.6,57.9
RX2_N: J12.6 U21.13 | length 11.5
  L1 - TOP w0.102: J12.6@19.79,53.695 18.605,53.695 18.3,54 18.3,54.475 18.573,54.748 27.002,54.748 27.049,54.7 U21.13@27.6,54.7
RX2_P: J12.3 U21.12 | length 11.7
  L1 - TOP w0.102: J12.3@17.25,57.505 17.25,57.05 19.248,55.052 27.002,55.052 27.049,55.1 U21.12@27.6,55.1
RX_3U: U27.D9 U30.6 | length 70.6
  L1 - TOP w0.165: v1(10.825,25.95) 7.5,22.625 7.5,17.2 9.5,15.2 11.8,15.2 U27.D9@12.2,14.8 ; v1(41.8,56.8) 42.825,56.8 U30.6@42.875,56.85
  L3 - SIG w0.14: v1(10.825,25.95) 11.575,26.7 14.248,26.7 15.5,27.952 15.5,42.5 18.9,45.9 33.234,45.9 41.8,54.466 v1(41.8,56.8)
rxa1_n: C246.2 J13.6 R143.1 R194.1 | length 13.4
  L1 - TOP w0.102: R143.1@124.6,44.6 125.098,45.098 125.552,45.098 C246.2@125.9,44.75 126.248,45.098 126.752,45.098 R194.1@127.1,44.75 127.448,45.098 130.902,45.098 131.3,44.7 131.3,43.125 130.95,42.775 129.475,42.775 129.175,43.075 129.175,43.783 129.312,43.92 J13.6@130.21,43.92
rxa1_p: C244.2 J13.3 R142.1 R190.1 | length 13.2
  L1 - TOP w0.102: R142.1@124.6,45.9 125.097,45.403 125.552,45.403 C244.2@125.9,45.75 126.248,45.402 126.752,45.402 R190.1@127.1,45.75 127.448,45.402 131.029,45.402 131.605,44.826 131.605,41.255 J13.3@132.75,40.11
rxa_n: D14.2 D20.1 R143.2 U24.54 | length 11.5
  L1 - TOP w0.102: U24.54@116.1,48.25 116.2,48.25 116.298,48.348 117.921,48.348 119.195,47.074 119.195,46.174 119.284,46.084 120.321,45.048 121.302,45.048 D20.1@121.6,44.75 121.948,45.098 122.502,45.098 R143.2@123,44.6 122.385,43.985 D14.2@122.385,42.7
rxa_p: D13.2 D20.2 R142.2 U24.55 | length 11.4
  L1 - TOP w0.102: U24.55@116.1,48.75 116.25,48.75 116.348,48.652 118.048,48.652 119.5,47.2 119.5,46.3 120.448,45.352 121.302,45.352 D20.2@121.6,45.65 121.848,45.402 122.502,45.402 R142.2@123,45.9 122.385,46.515 D13.2@122.385,47.8
rxb1_n: C166.2 J14.6 R192.1 R260.1 | length 14.1
  L1 - TOP w0.102: R192.1@124.6,57.2 125.148,56.652 125.502,56.652 C166.2@125.9,57.05 126.297,56.652 126.702,56.652 R260.1@127.1,57.05 127.498,56.652 130.952,56.652 131.4,57.1 131.4,61.6 J14.6@130.21,62.79
rxb1_p: C165.2 J14.3 R191.1 R197.1 | length 14
  L1 - TOP w0.102: R191.1@124.6,55.8 125.148,56.348 125.502,56.348 C165.2@125.9,55.95 126.297,56.348 126.702,56.348 R197.1@127.1,55.95 127.498,56.348 131.079,56.348 131.705,56.974 131.705,60.255 131.925,60.475 132.43,60.475 132.7,60.205 132.7,59.03 J14.3@132.75,58.98
rxb_n: D18.2 D22.2 R192.2 U24.61 | length 12.9
  L1 - TOP w0.1: U24.61@116.1,51.75 116.198,51.652 118.052,51.652 119.095,52.695 119.095,54.774 120.974,56.652 121.402,56.652 D22.2@121.7,56.95 121.998,56.652 122.452,56.652 R192.2@123,57.2 122.385,57.815 D18.2@122.385,59.1
rxb_p: D17.2 D22.1 R191.2 U24.60 | length 12.9
  L1 - TOP w0.1: U24.60@116.1,51.25 116.198,51.348 118.179,51.348 119.4,52.569 119.4,54.648 121.1,56.348 121.402,56.348 D22.1@121.7,56.05 121.998,56.348 122.452,56.348 R191.2@123,55.8 122.385,55.185 D17.2@122.385,53.9
SENSE1_N: R15.4 U3.A2 | length 5.7
  L1 - TOP w0.2: R15.4@38,70 37.275,70 36.75,70.525 36.75,71.1 37.05,71.4 38.707,71.4 39.25,71.943 U3.A2@39.25,72.75
SENSE1_P: R15.3 U3.A3 | length 5.7
  L1 - TOP w0.2: R15.3@35,70 35.725,70 36.25,70.525 36.25,71.307 36.843,71.9 38.5,71.9 38.75,72.15 U3.A3@38.75,72.75
SENSE2_N: R16.4 U3.B1 | length 5.7
  L1 - TOP w0.2: U3.B1@39.75,73.25 40.557,73.25 41.1,72.707 41.1,71.05 41.4,70.75 41.975,70.75 42.5,71.275 R16.4@42.5,72
SENSE2_P: R16.3 U3.A1 | length 5.7
  L1 - TOP w0.2: U3.A1@39.75,72.75 40.35,72.75 40.6,72.5 40.6,70.843 41.193,70.25 41.975,70.25 42.5,69.725 R16.3@42.5,69
SENSE3_N: R18.4 U3.C1 | length 5.7
  L1 - TOP w0.2: U3.C1@39.75,73.75 40.557,73.75 41.1,74.293 41.1,75.95 41.4,76.25 41.975,76.25 42.5,75.725 R18.4@42.5,75
SENSE3_P: R18.3 U3.D1 | length 5.7
  L1 - TOP w0.2: U3.D1@39.75,74.25 40.35,74.25 40.6,74.5 40.6,76.157 41.193,76.75 41.975,76.75 42.5,77.275 R18.3@42.5,78
SENSE4_N: R17.4 U3.D2 | length 5.7
  L1 - TOP w0.2: R17.4@38,77 37.275,77 36.75,76.475 36.75,75.9 37.05,75.6 38.707,75.6 38.711,75.596 38.711,75.593 39.004,75.3 39.007,75.3 39.25,75.057 U3.D2@39.25,74.25
SENSE4_P: R17.3 U3.D3 | length 5.7
  L1 - TOP w0.2: R17.3@35,77 35.725,77 36.25,76.475 36.25,75.693 36.843,75.1 38.5,75.1 38.75,74.85 U3.D3@38.75,74.25
SHDN: R6.1 U4.R1 | length 64.2
  L1 - TOP w0.125: v1(56.8,43.1) 56.8,44.54 57.46,45.2 U4.R1@57.6,45.2
  L4 - SIG w0.125: v1(21.5,73.9) 21.9,73.5 21.9,52 30.8,43.1 36.024,43.1 36.029,43.105 36.361,43.105 36.366,43.1 v1(56.8,43.1)
  L6 - BOT w0.125: v1(21.5,73.9) 21.5,74.5 R6.1@21.8,74.8
SUSPEND_N: R152.1 U19.28 | length 16.9
  L1 - TOP w0.165: U19.28@31.65,31.8 v1(33,31.8) ; R152.1@33.4,45.155 33.955,44.6 v1@34.459,44.6 ; v1@34.5,44.559 v1@34.459,44.6 ; v1(34.5,44.6) v1@34.459,44.6
  L6 - BOT w0.165: v1(33,31.8) 34.5,33.3 34.5,36.8 33.6,37.7 33.6,43.7 v1(34.5,44.6)
TCKIN: R221.2 U27.H4 U31.7 | length 15.4
  L1 - TOP w0.165: U27.H4@16.2,18 v1(16.6,18.4) 20.6,18.4 20.7,18.5 25.3,18.5 26.2,19.4 26.2,21.8 25.85,22.15 U31.7@25.45,22.15
  L6 - BOT w0.165: R221.2@15.15,18.7 16.3,18.7 v1(16.6,18.4)
TCKOUT: R221.1 U27.H8 U27.K7 | length 4.7
  L1 - TOP w0.165: v1(13.4,17.6) U27.H8@13,18 12.6,18.4 12.6,19.1 12.7,19.2 13.4,19.2 U27.K7@13.8,19.6
  L6 - BOT w0.165: v1(13.4,17.6) 14.25,18.45 R221.1@14.25,18.7
TDIIN: R222.2 U27.H5 U31.15 | length 12.3
  L1 - TOP w0.165: U27.H5@15.4,18 15.8,18.4 v1(15.8,22) 16.05,22.25 18.55,22.25 19.15,21.65 U31.15@22.55,21.65 U31.15@22.8,21.65
  L6 - BOT w0.165: R222.2@15.05,22 v1(15.8,22)
TDIOUT: R222.1 U27.K8 | length 3.3
  L1 - TOP w0.165: U27.K8@13,19.6 13.3,19.9 v1(13.3,21.9)
  L6 - BOT w0.165: v1(13.3,21.9) 13.4,22 R222.1@14.15,22
TDOIN: U27.J8 U31.3 | length 13.6
  L1 - TOP w0.165: U27.J8@13,18.8 v1(13.4,18.4) ; v1(19.9,19) 23.8,19 24.25,19.45 U31.3@24.25,20.45
  L6 - BOT w0.165: v1(13.4,18.4) 13.4,18.8 13.9,19.3 15.9,19.3 16.2,19.6 17.3,19.6 17.9,19 v1(19.9,19)
TMSIN: R223.1 U27.H6 U31.11 | length 16.6
  L1 - TOP w0.165: U27.H6@14.6,18 15,18.4 v1(15,20.2) 15,23.2 16.5,24.7 23.513,24.7 23.75,24.463 U31.11@23.75,23.35
  L6 - BOT w0.165: v1(15,20.2) 15,20.75 R223.1@15.05,20.8
TMSOUT: R223.2 U27.H7 | length 3
  L1 - TOP w0.165: U27.H7@13.8,18 14.2,18.4 14.2,20.1 v1(14.15,20.15)
  L6 - BOT w0.165: v1(14.15,20.15) R223.2@14.15,20.8
TR0_N: J10.8 U19.2 | length 8.6
  L1 - TOP w0.102: J10.8@19.79,39.79 19.41,39.79 18.8,40.4 18.8,40.8 19,41 20.869,41 23.421,38.448 24.502,38.448 U19.2@24.6,38.35
TR0_P: J10.9 U19.1 | length 8.5
  L1 - TOP w0.102: J10.9@17.25,41.06 18.629,41.06 18.874,41.305 20.995,41.305 21.095,41.205 23.548,38.752 24.502,38.752 U19.1@24.6,38.85
TR1_N: J10.6 U19.5 | length 8.1
  L1 - TOP w0.102: J10.6@19.79,37.25 19.45,37.25 18.8,37.9 18.8,38.2 19,38.4 21.469,38.4 22.921,36.948 24.502,36.948 U19.5@24.6,36.85
TR1_P: J10.7 U19.4 | length 8.3
  L1 - TOP w0.102: J10.7@17.25,38.52 17.47,38.3 18.469,38.3 18.874,38.705 21.595,38.705 23.048,37.252 24.502,37.252 U19.4@24.6,37.35
TR2_N: J10.4 U19.8 | length 7.7
  L1 - TOP w0.102: J10.4@19.79,34.71 19.169,34.71 18.725,35.154 18.725,35.425 19.095,35.795 22.526,35.795 22.874,35.448 24.502,35.448 U19.8@24.6,35.35
TR2_P: J10.5 U19.7 | length 7.8
  L1 - TOP w0.102: J10.5@17.25,35.98 17.514,35.716 18.584,35.716 18.969,36.1 22.652,36.1 23,35.752 24.502,35.752 U19.7@24.6,35.85
TR3_N: J10.2 U19.11 | length 7.7
  L1 - TOP w0.102: J10.2@19.79,32.17 19.23,32.17 18.9,32.5 18.9,33 19.195,33.295 21.595,33.295 22.248,33.948 24.502,33.948 U19.11@24.6,33.85
TR3_P: J10.3 U19.10 | length 7.9
  L1 - TOP w0.102: J10.3@17.25,33.44 17.474,33.216 18.684,33.216 19.069,33.6 21.469,33.6 22.121,34.252 24.502,34.252 U19.10@24.6,34.35
TRESIN: R215.2 U27.G8 U28.3 | length 4.3
  L1 - TOP w0.165: v1(12.6,17.6) U27.G8@13,17.2
  L6 - BOT w0.165: R215.2@11.95,17.7 12.5,17.7 v1(12.6,17.6) 12.6,19.778 12.275,20.103 12.275,20.125 12.1,20.3 U28.3@12,20.3
TRESOUT: R215.1 U27.G10 | length 2.5
  L1 - TOP w0.165: v1(10.1,17.6) 10.2,17.6 10.6,17.2 U27.G10@11.4,17.2
  L6 - BOT w0.165: v1(10.1,17.6) 10.95,17.6 R215.1@11.05,17.7
TRSTIN: R214.1 U27.J10 | length 1.2
  L1 - TOP w0.165: v1(11,18.4) U27.J10@11.4,18.8
  L6 - BOT w0.165: v1(11,18.4) R214.1@11,19
TRSTOUT: R214.2 U27.H9 | length 1.2
  L1 - TOP w0.165: v1(11.8,18.4) U27.H9@12.2,18
  L6 - BOT w0.165: v1(11.8,18.4) 11.8,18.9 R214.2@11.9,19
TX1_N: J11.2 U21.3 | length 29.3
  L1 - TOP w0.102: J11.2@19.79,77.775 19.249,77.775 18.8,78.224 18.8,78.675 19.3,79.175 20.095,79.175 21.045,78.225 21.045,77.33 21.92,76.455 21.92,62.645 22.445,62.12 22.445,59.505 23.202,58.748 27.002,58.748 27.049,58.7 U21.3@27.6,58.7
TX1_P: J11.1 U21.2 | length 29.3
  L1 - TOP w0.102: J11.1@17.25,79.045 17.445,78.85 18.544,78.85 19.174,79.48 20.221,79.48 21.35,78.351 21.35,77.456 22.225,76.581 22.225,62.85 22.75,62.325 22.75,59.631 23.329,59.052 27.002,59.052 27.049,59.1 U21.2@27.6,59.1
TX2_N: J12.2 U21.10 | length 13.4
  L1 - TOP w0.102: J12.2@19.79,58.775 19.324,58.775 18.775,59.324 18.775,59.6 19.35,60.175 20.375,60.175 20.795,59.755 20.795,58.024 22.871,55.948 27.002,55.948 27.049,55.9 U21.10@27.6,55.9
TX2_P: J12.1 U21.9 | length 13.3
  L1 - TOP w0.102: J12.1@17.25,60.045 18.789,60.045 19.224,60.48 20.501,60.48 21.1,59.881 21.1,58.15 22.998,56.252 27.002,56.252 27.049,56.3 U21.9@27.6,56.3
TX_3U: U27.D10 U30.5 | length 70.1
  L1 - TOP w0.165: v1(9.6,25.925) 6.725,23.05 6.725,17.075 9,14.8 U27.D10@11.4,14.8 ; v1(41.8,57.4) 42.825,57.4 U30.5@42.875,57.35
  L3 - SIG w0.14: v1(9.6,25.925) 9.6,26.7 14.1,31.2 14.1,42.5 18.3,46.7 32.9,46.7 41.1,54.9 41.1,56.7 v1(41.8,57.4)
txa1_n: C242.2 J13.2 R141.1 R188.1 | length 15.7
  L6 - BOT w0.102: R141.1@124.6,44.6 125.098,45.098 125.553,45.098 C242.2@125.9,44.75 126.248,45.098 126.752,45.098 R188.1@127.1,44.75 127.448,45.098 130.902,45.098 131.3,44.7 131.3,39.4 131.3,38.2 131.1,38 130.8,38 130.3,38.5 J13.2@130.3,38.75
txa1_p: C240.2 J13.1 R140.1 R182.1 | length 15.8
  L6 - BOT w0.102: R140.1@124.6,45.9 125.098,45.402 125.552,45.402 C240.2@125.9,45.75 126.248,45.403 126.752,45.403 R182.1@127.1,45.75 127.448,45.403 131.028,45.403 131.605,44.826 131.605,38.715 J13.1@132.75,37.57
txa_n: D12.2 D19.2 R141.2 U24.52 | length 10.6
  L1 - TOP w0.102: U24.52@116.1,47.25 116.198,47.348 117.352,47.348 v1(117.5,47.2)
  L6 - BOT w0.102: v1(117.5,47.2) 117.648,47.348 117.8,47.348 120.1,45.048 121.302,45.048 D19.2@121.6,44.75 121.898,45.048 122.552,45.048 R141.2@123,44.6 122.385,43.985 D12.2@122.385,42.7
txa_p: D11.2 D19.1 R140.2 U24.53 | length 10.6
  L1 - TOP w0.102: U24.53@116.1,47.75 116.198,47.652 117.352,47.652 v1(117.5,47.8)
  L6 - BOT w0.102: v1(117.5,47.8) 117.648,47.652 117.926,47.652 120.226,45.352 121.302,45.352 D19.1@121.6,45.65 121.898,45.352 122.452,45.352 R140.2@123,45.9 122.385,46.515 D11.2@122.385,47.8
txb1_n: C164.2 J14.2 R189.1 R195.1 | length 9.1
  L6 - BOT w0.102: R189.1@124.6,57.2 125.148,56.652 125.502,56.652 C164.2@125.9,57.05 126.297,56.652 126.702,56.652 R195.1@127.1,57.05 127.498,56.652 130.952,56.652 131.2,56.9 131.2,57.2 130.69,57.71 J14.2@130.21,57.71
txb1_p: C162.2 J14.1 R183.1 R193.1 | length 9.3
  L6 - BOT w0.102: R183.1@124.6,55.8 125.148,56.348 125.502,56.348 C162.2@125.9,55.95 126.297,56.348 126.702,56.348 R193.1@127.1,55.95 127.497,56.348 131.079,56.348 131.431,56.7 132.49,56.7 J14.1@132.75,56.44
txb_n: D16.2 D21.2 R189.2 U24.63 | length 12.7
  L1 - TOP w0.102: U24.63@116.1,52.75 116.198,52.652 117.352,52.652 v1(117.5,52.8)
  L6 - BOT w0.1: v1(117.5,52.8) 117.648,52.652 118,52.652 118.7,53.352 118.7,55.731 119.621,56.652 121.402,56.652 D21.2@121.7,56.95 121.998,56.652 122.452,56.652 R189.2@123,57.2 122.385,57.815 D16.2@122.385,59.1
txb_p: D15.2 D21.1 R183.2 U24.62 | length 12.7
  L1 - TOP w0.102: U24.62@116.1,52.25 116.198,52.348 117.352,52.348 v1(117.5,52.2)
  L6 - BOT w0.1: v1(117.5,52.2) 117.648,52.348 118.126,52.348 119.005,53.226 119.005,55.605 119.748,56.348 121.402,56.348 D21.1@121.7,56.05 121.998,56.348 122.452,56.348 R183.2@123,55.8 122.385,55.185 D15.2@122.385,53.9
USBD1_n: J7.2 U15.1 | length 14.4
  L1 - TOP w0.135: J7.2@44.26,15.63 45.085,16.455 ; J7.2@44.967,15.63 45.085,15.748 ; 45.085,14.707 45.085,15.748 ; 45.085,16.51 45.085,16.455 ; U15.1@52.83,21.55 52.911,21.55 52.911,20.7 51.786,19.575 46.997,19.575 45.087,17.665 45.087,16.457 45.085,16.455 ; 45.085,15.748 45.085,16.455
USBD1_p: J7.3 U15.2 | length 14.4
  L1 - TOP w0.135: 45.423,14.707 45.423,15.74 ; 45.423,16.561 45.423,15.74 ; J7.3@45.533,15.63 45.423,15.74 ; J7.3@46.26,15.63 45.425,16.465 45.425,17.525 47.137,19.237 51.926,19.237 53.249,20.56 53.249,21.55 U15.2@53.33,21.55
USBD2_n: J7.6 U15.3 | length 15.4
  L1 - TOP w0.135: J7.6@44.26,13.01 44.26,13.26 45.326,14.326 47.126,14.326 47.362,14.562 47.362,16.69 49.322,18.65 52.211,18.65 53.911,20.35 53.911,21.55 U15.3@53.83,21.55
USBD2_p: J7.7 U15.4 | length 15.1
  L1 - TOP w0.135: J7.7@46.26,13.01 47.21,13.01 47.362,13.162 47.362,14.084 47.7,14.422 47.7,16.55 49.462,18.312 52.351,18.312 52.937,18.898 53.117,18.898 53.365,18.65 53.64,18.65 53.8,18.81 53.8,19.112 53.565,19.347 53.565,19.526 54.249,20.21 54.249,21.55 U15.4@54.33,21.55
USBD3_n: J8.2 U15.6 | length 14.6
  L1 - TOP w0.135: U15.6@55.33,21.55 55.411,21.55 55.411,20.358 57.718,18.052 63.055,18.052 64.237,16.87 64.237,15.748 ; J8.2@63.4,15.63 64.119,15.63 64.237,15.748 ; 64.237,14.707 64.237,15.748
USBD3_p: J8.3 U15.7 | length 14.6
  L1 - TOP w0.135: U15.7@55.83,21.55 55.749,21.55 55.749,20.498 57.858,18.39 63.195,18.39 64.574,17.01 64.574,15.74 ; 64.574,14.707 64.574,15.74 ; J8.3@65.4,15.63 64.685,15.63 64.574,15.74
USBD4_n: J8.6 U15.8 | length 18.9
  L1 - TOP w0.135: U15.8@56.33,21.55 56.406,21.55 56.406,20.434 57.917,18.923 64.338,18.923 66.502,16.759 66.502,14.562 66.266,14.326 64.466,14.326 63.4,13.26 J8.6@63.4,13.01
USBD4_p: J8.7 U15.9 | length 18.7
  L1 - TOP w0.135: U15.9@56.83,21.55 56.749,21.55 56.744,21.544 56.744,20.574 58.057,19.261 64.478,19.261 65.535,18.204 65.714,18.204 65.935,18.425 66.25,18.425 66.4,18.275 66.4,17.993 66.163,17.756 66.163,17.576 66.84,16.899 66.84,14.422 66.5,14.082 66.5,13.114 66.396,13.01 J8.7@65.4,13.01
USBD_JLINK_N: J16.2 R203.1 U27.D2 | length 18.5
  L1 - TOP w0.135: J16.2@4.9,10.75 4.9,10.594 5.944,10.594 v1(6.1,10.75)
  L1 - TOP w0.165: U27.D2@17.8,14.8 v1(18.2,14.4)
  L6 - BOT w0.135: v1(6.1,10.75) 6.287,10.563 8.562,10.563 8.95,10.175 15.875,10.175 16.537,10.837 16.537,13.465 17.241,14.169 17.969,14.169 v1(18.2,14.4) v1@18.275,14.325
  L6 - BOT w0.165: v1@18.275,14.325 18.475,14.325 R203.1@18.85,14.7
USBD_JLINK_P: J16.3 R204.1 U27.C2 | length 18.4
  L1 - TOP w0.135: J16.3@4.9,10.1 4.9,10.256 5.944,10.256 v1(6.1,10.1)
  L1 - TOP w0.165: U27.C2@17.8,14 v1(18.2,13.6)
  L6 - BOT w0.135: v1(6.1,10.1) 6.225,10.225 8.422,10.225 8.81,9.837 16.015,9.837 16.875,10.697 16.875,13.325 17.381,13.831 17.969,13.831 v1(18.2,13.6) v1@18.275,13.675
  L6 - BOT w0.165: v1@18.275,13.675 18.475,13.675 R204.1@18.85,13.3
VBUS_JLINK: C4.2 J16.1 Q2.1 R11.1 | length 100.7
  L1 - TOP w0.4: J16.1@4.9,11.4 v1(6.5,11.4) v1(6.9,11.4) v1(7.3,11.4)
  L6 - BOT w1: 7,12.8 7,25.725 1.1,31.625 1.1,82.2 3.825,84.925 3.825,93.125 5.9,95.2 14.7,95.2 15.9,94 R11.1@15.9,93
VDD12TX: C288.2 C289.2 FB25.2 U24.56 U24.59 | length 8.5
  L1 - TOP w0.127: U24.59@116.1,50.75 U24.59@116.186,50.836
  L1 - TOP w0.3: U24.56@116.1,49.25 116.875,49.25 v1(116.975,49.15) ; U24.59@116.1,50.75 116.85,50.75 v1(116.95,50.85)
  L6 - BOT w0.3: v1(116.95,50.85) 118.1,50.85 C288.2@118.25,50.7 ; v1(116.975,49.15) 118.1,49.15 C289.2@118.25,49.3
  L6 - BOT w0.4: C289.2@118.25,49.3 118.3,49.35 118.3,49.95 ; C288.2@118.25,50.7 118.3,50.65 118.3,50.05
  L6 - BOT w0.5: 118.35,50 FB25.2@120.9,50
VDD33BIAS: C286.2 C287.2 FB22.2 U24.58 | length 7.4
  L1 - TOP w0.3: U24.58@116.1,50.25 117.25,50.25 117.5,50 v1(117.7,50)
  L1 - TOP w0.4: v1(117.7,50) FB22.2@120.9,50
  L6 - BOT w0.4: C287.2@116.05,51.3 116.05,50.75 C286.2@116.8,50 v1(117.7,50)
VDD33TXRX1: C227.2 C232.2 C234.2 C248.2 FB24.2 J13.4 J13.5 R182.2 R188.2 R190.2 R194.2 U24.51 | length 11.4
  L1 - TOP w0.3: U24.51@116.1,46.75 v1(117.075,46.75)
  L1 - TOP w0.5: v1(127.1,43.15) R194.2@127.1,43.85 ; R190.2@127.1,46.65 v1(127.1,47.35)
  L6 - BOT w0.3: C227.2@116.3,44.2 116.25,44.25 C232.2@116.25,45.5 C234.2@116.25,46.75 v1(117.075,46.75)
  L6 - BOT w0.4: FB24.2@116.3,42.775 117.175,42.775 v1(117.35,42.6) ; C227.2@116.3,44.2 v1(117.35,44.2) ; C232.2@116.3,45.475 v1(117.25,45.475)
  L6 - BOT w0.5: v1(119.7,39.5) C248.2@119.7,40.6 ; v1(127.1,43.15) R188.2@127.1,43.85 ; R182.2@127.1,46.65 v1(127.1,47.35)
VDD33TXRX2: C181.2 C226.2 C231.2 C233.2 FB23.2 J14.4 J14.5 R193.2 R195.2 R197.2 R260.2 U24.64 | length 9.1
  L1 - TOP w0.3: U24.64@116.1,53.25 v1(117.075,53.25)
  L1 - TOP w0.5: v1(127.1,54.35) R197.2@127.1,55.05 ; R260.2@127.1,57.95 v1(127.1,58.65)
  L6 - BOT w0.3: C233.2@116,53.75 116.575,53.75 v1(117.075,53.25) ; v1(119.9,58.4) C181.2@119.9,59.4
  L6 - BOT w0.4: C231.2@116.25,54.825 v1(117.2,54.825) ; C226.2@116.25,56.1 v1(117.3,56.1) ; FB23.2@116.25,57.525 v1(117.3,57.525)
  L6 - BOT w0.5: v1(127.1,54.35) R193.2@127.1,55.05 ; R195.2@127.1,57.95 v1(127.1,58.65)
VDD_3V3_JLINK: C250.2 C253.2 C256.2 C257.2 C259.2 C261.2 C263.2 C265.2 C267.2 C269.2 C271.2 C273.2 C276.2 D10.2 J15.16 J17.1 R199.2 R205.1 R207.1 R217.2 R218.2 R219.2 R220.2 U26.1 U26.2 U27.A8 U27.B3 U27.C10 U27.E6 U27.F3 U27.F5 U27.J3 U27.K2 U27.K4 U28.1 U31.14 Y11.1 Y11.4 | length 39.5
  L1 - TOP w0.3: v1(18.5,8.7) 18.5,9.175 R199.2@18.875,9.55 ; v1(20.95,22.85) C276.2@20.95,22.25 21.05,22.15 U31.14@22.55,22.15 ; R219.2@22.8,13.525 22.8,13.5 v1(23.4,12.9)
  L1 - TOP w0.4: J15.16@10.825,3.625 v1(10.825,6.475) ; v1(11,13.6) U27.C10@11.4,14 ; v1(12.9,11.2) 13,11.3 U27.A8@13,12.4 ; U27.E6@14.6,15.6 v1(15,15.2) ; U27.F5@15.4,16.4 v1(15.8,16.8) ; U27.K4@16.2,19.6 v1(16.6,19.2) U27.J3@17,18.8 ; U27.B3@17,13.2 v1(17.4,12.8) ; U27.F3@17,16.4 v1(17.4,16.8) ; U27.K2@17.8,19.6 v1(18.2,20) ; v1(22.375,5.525) D10.2@22.375,6.875 ; Y11.4@26.175,12.225 26.175,14.864 26.45,15.139 C250.2@26.45,15.55 R218.2@26.45,17.05
  L5 - VCC w1: v1(23.4,12.9) 24.2,13.7 25.2,13.7 v1(26.2,14.7)
  L6 - BOT w0.15: R220.2@5.15,19 v1(5.8,19) ; R217.2@5.15,23 v1(5.8,23) ; U28.1@11.975,21 v1(11.975,21.9) 11.975,22.625 C273.2@12.05,22.7
  L6 - BOT w0.2: U26.2@17.125,24.9 U26.1@17.125,25.3 ; C256.2@18.25,25.1 18.5,25.35 v1(18.5,26) 19.6,26 C253.2@19.9,25.7
  L6 - BOT w0.4: C265.2@9.95,14.2 R205.1@11.05,14.2 11,14.15 v1(11,13.6) ; v1(10.1,15.925) 10.525,15.925 11.05,15.4 R207.1@11.05,15.3 R205.1@11.05,14.4 ; C267.2@12.15,11 12.35,11.2 v1(12.9,11.2) 13.7,11.2 C263.2@13.8,11.1 ; C269.2@14.2,14.85 14.65,14.85 v1(15,15.2) ; C259.2@15.35,16 15.35,16.15 15.8,16.6 v1(15.8,16.8) ; 17.241,25.1 18.25,25.1 C256.2@18.366,25.1 ; v1(17.4,12.8) 17.4,12.25 C261.2@17.5,12.15 ; v1(17.4,16.8) C257.2@18.075,16.8 ; C271.2@17.85,20.7 18.2,20.35 v1(18.2,20)
VDD_3V3_WILC: C305.2 FB27.1 U37.7 U37.8 | length 3.4
  L1 - TOP w0.5: FB27.1@118.9,17.95 C305.2@120.5,17.95 U37.8@121.95,17.95 U37.7@122.35,17.95
VDD_LED: C10.2 LD7.2 U2.21 | length 120.1
  L1 - TOP w0.3: U2.21@29.5,79.25 30.537,79.25 v1(31.337,80.05) 31.337,80.063 31.85,80.575 C10.2@31.85,80.6
  L1 - TOP w0.5: LD7.2@85.8,28.85 87.15,28.85 v1(87.2,28.9)
  L5 - VCC w0.5: v1(31.337,80.05) 33.775,80.05 36.025,82.3 53.3,82.3 61.3,74.3 89.6,74.3 97.9,66 97.9,40.2 96.035,38.335 96.035,37.735 v1(87.2,28.9)
VDD_MAIN_5V: C3.2 C8.2 C11.2 C13.2 C15.2 C17.2 C19.2 C22.2 C24.2 C131.2 C132.2 C144.1 C145.1 C252.2 C290.1 C303.1 Q1.4 Q2.4 R7.2 R9.2 R14.2 R72.2 R236.1 R237.1 R238.1 U2.4 U2.10 U2.15 U2.20 U2.26 U2.31 U3.A4 U13.3 U14.3 U16.7 U17.7 U26.4 U26.6 U37.1 U37.2 | length 662.3
  L1 - TOP w0.3: v1(23.85,79.25) U2.4@24.5,79.25 ; v1(24.7,75.7) v1(25.2,75.7) 25.425,75.7 25.75,76.025 U2.10@25.75,76.5 ; v1(24.7,82.3) v1(25.2,82.3) 25.425,82.3 25.75,81.975 U2.31@25.75,81.5 ; U2.15@28.25,76.5 28.25,76.025 28.575,75.7 v1(28.8,75.7) v1(29.3,75.7) ; U2.26@28.25,81.5 28.25,81.975 28.575,82.3 v1(28.8,82.3) v1(29.3,82.3) ; U2.20@29.5,78.75 v1(30.3,78.75) v1(31.1,78.75) C8.2@31.85,79.5 ; C22.2@36.45,72.9 v1(36.95,72.4) 37.9,72.4 U3.A4@38.25,72.75
  L1 - TOP w0.35: v1(46.025,73.169) U13.3@46.025,74.05 ; v1@53.525,73.369 U14.3@53.525,74.05
  L1 - TOP w0.4: R7.2@32.75,76.2 v1(33.325,76.2)
  L1 - TOP w0.5: v1(120.1,13.6) 120.5,13.6 ; v1(120.5,13.2) 120.5,13.6 ; v1(120.9,13.6) 120.5,13.6 ; U37.2@122.35,14.95 U37.1@121.95,14.95 C303.1@120.5,14.95 120.5,13.6
  L3 - SIG w1: v1(24.1,92.2) v1(24.1,90.1) 24.1,89.1 9.7,74.7 6.5,74.7 3.1,71.3 3.1,30.3 8.6,24.8 13.7,24.8 v1(14.7,23.8) 15.6,22.9 17.9,22.9 23.5,17.3 27.9,17.3 38,7.2 40.7,7.2 v1(43.9,4) 43.91,3.99 v1(63.04,3.99) v1(63.96,3.99) 75.7,3.99 82.91,11.2 118.1,11.2 120.5,13.6
  L4 - SIG w1: v1(24.1,92.2) v1(24.1,90.1) 24.1,89.1 9.7,74.7 6.5,74.7 3.1,71.3 3.1,30.3 8.6,24.8 13.7,24.8 v1(14.7,23.8) 15.6,22.9 17.9,22.9 23.5,17.3 27.9,17.3 38,7.2 40.7,7.2 v1(43.9,4) 43.91,3.99 v1(63.04,3.99) v1(63.96,3.99) 75.7,3.99 82.91,11.2 118.1,11.2 120.5,13.6
  L5 - VCC w0.4: v1(30.3,78.75) v1(31.1,78.75)
  L6 - BOT w0.2: C252.2@14.625,24.5 14.7,24.5 U26.4@16.075,24.5 ; C252.2@14.625,25.2 15.686,25.2 15.786,25.3 U26.6@16.075,25.3
  L6 - BOT w0.3: v1(19.4,94.8) 19.413,94.787 Q2.4@19.413,94.15 ; v1(22.8,94.8) 22.813,94.787 Q1.4@22.813,94.15 ; C24.2@36.45,72.9 v1(36.95,72.4) 37.7,72.4 39.4,74.1 39.6,74.1
  L6 - BOT w0.35: R14.2@16.9,86.2 v1(17.8,86.2) ; 38.3,75.4 39.6,74.1 40.2,73.5 44.4,73.5 44.819,73.919 C131.2@46.025,73.919 ; C131.2@46.019,73.975 C131.2@46.025,73.969 ; v1(46.025,73.169) C131.2@46.025,73.919 ; v1(53.525,73.269) C132.2@53.525,73.919 46.075,73.919 C131.2@46.025,73.969 ; C131.2@46.025,73.919 C131.2@46.025,73.969
  L6 - BOT w0.4: v1(14.7,23.8) 14.7,24.5 C252.2@14.7,24.85 C252.2@14.7,24.9 ; v1(23.85,79.25) C3.2@24.5,79.25 ; v1(24.7,82.3) v1(25.2,82.3) ; v1(28.8,75.7) v1(29.3,75.7) ; v1(28.8,82.3) v1(29.3,82.3) ; R72.2@32.75,75.1 33.825,75.1 34.125,75.4 ; R9.2@32.75,76.2 v1(33.325,76.2) 34.125,75.4 ; 38.3,75.4 34.125,75.4
  L6 - BOT w0.5: 24.95,82.4 C17.2@24.95,83.05 ; 29.05,82.4 C15.2@29.05,83.05
  L6 - BOT w0.6: C144.1@41.5,1 41.5,1.6 v1(43.9,4) v1(44.82,4) 45.895,5.075 U16.7@45.895,6.71 ; C145.1@61.05,1 61.05,2 v1(63.04,3.99) v1(63.96,3.99) 65.035,5.065 U17.7@65.035,6.7
  L6 - BOT w0.9: 24.95,75.5 24.95,75.6 ; 29.05,75.5 29.05,75.6
  L6 - BOT w1: 23.715,94.315 28.4,99 86.8,99 ; R236.1@86.9,79.8 86.9,98.9 86.8,99 ; R237.1@115.9,79.8 115.9,98.8 116,98.9 ; R238.1@144.9,79.8 144.9,95.1 141,99 86.8,99
  other v1: 120.5,14 38.9,83.4 41.5,83.4 38.9,84.4 41.5,84.4 38.9,85.4 41.5,85.4 23.475,92.7 23.475,94.3 20.2,94.8 21,94.8 21.9,94.8 19.4,95.7
VDDANA: C31.2 C34.2 FB8.2 R68.1 U4.K3 U4.L5 | length 7.5
  L1 - TOP w0.2: v1(58.8,48.8) U4.K3@59.2,49.2 ; v1(60.4,48) U4.L5@60.8,48.4
  L6 - BOT w0.2: FB8.2@55.1,49 56.15,49 R68.1@56.3,48.85 56.65,49.2 58.4,49.2 v1(58.8,48.8) 59.062,48.538 59.2,48.4 C31.2@60,48.4 ; C31.2@60,48.538 C31.2@60,48.4 ; v1(60.4,48) C31.2@60,48.4
  L6 - BOT w0.3: C34.2@59.062,48.4 C34.2@59.062,48.538 ; C31.2@60,48.4 C31.2@60,48.538
VDDAUDIOPLL: C57.2 C61.2 L7.2 U4.T3 | length 3.4
  L1 - TOP w0.4: v1(58.8,44) U4.T3@59.2,44.4
  L6 - BOT w0.4: L7.2@58.2,41.6 58.5,41.9 58.5,44 v1(58.8,44)
VDDBU: C56.2 J2.1 R75.1 R256.2 U4.N7 | length 110.7
  L1 - TOP w0.2: U4.N7@62.4,46.8 v1(62.8,46.4)
  L1 - TOP w0.5: J2.1@45.47,39.6 45.52,39.55 R75.1@47.9,39.55
  L4 - SIG w0.4: v1(33.7,95.9) 18.6,80.8 18.6,49.7 23,45.3 25.6,45.3 29.6,41.3 31.4,41.3 32.1,40.6 37.1,40.6 37.8,41.3 43.77,41.3 J2.1@45.47,39.6
  L5 - VCC w0.2: v1(56.6,41.4) 56.4,41.6 56.4,43.8 58.6,46 62.4,46 v1(62.8,46.4)
  L6 - BOT w0.3: v1(62.8,46.4) 63.2,46.8 C56.2@63.2,46.938
  L6 - BOT w0.4: v1(33.7,95.9) 34.7,95.9 R256.2@34.75,95.85 ; J2.1@45.47,39.6 46.27,40.4 55.6,40.4 v1(56.6,41.4)
VDDCORE: C29.2 C32.2 C35.2 C39.2 C42.2 C44.2 C48.2 C53.2 R18.2 U4.D7 U4.D9 U4.H3 U4.K13 U4.N5 U4.N9 | length 42.7
  L1 - TOP w0.2: v1(58.8,51.2) U4.H3@59.2,50.8 ; v1(60.4,46.4) U4.N5@60.8,46.8 ; v1(62,54.4) U4.D7@62.4,54 ; v1(63.6,53.6) U4.D9@64,54 ; U4.N9@64,46.8 v1(64.4,46.4) ; U4.K13@67.2,49.2 v1(67.6,49.6)
  L1 - TOP w0.5: R18.2@41.9,75 41.9,74.2 v1(42.1,74) v1(42.9,74) 43.1,74.2 R18.2@43.1,75
  L5 - VCC w0.2: 64.2,49.2 67.176,49.2 67.271,49.294 67.294,49.294 v1(67.6,49.6)
  L5 - VCC w1.5: 42.3,74.4 47.6,74.4 49.7,72.3 49.7,71.15 57.8,63.05 58.75,63.05 60.1,61.7 60.1,59.5
  L6 - BOT w0.3: C53.2@58.538,50.8 58.538,50.938 v1(58.8,51.2) ; C39.2@60,46.938 60,46.8 v1(60.4,46.4) ; v1(62,54.4) 62.262,54.662 C48.2@62.4,54.662 ; v1(63.6,53.6) 63.862,53.862 C42.2@64,53.862 ; C35.2@64,46.938 64,46.8 v1(64.4,46.4) ; C44.2@67.062,50 67.2,50 v1(67.6,49.6)
  L6 - BOT w0.4: v1(42.1,74) 42.5,74 ; C29.2@42.5,75.45 42.5,74 ; v1(42.9,74) 42.5,74
  L6 - BOT w0.5: v1(58,58) 58.85,58 C32.2@58.95,58.1
  other v1: 43.7,74.1 43.7,74.8
VDDCR: C236.2 C237.2 C238.2 C239.2 FB25.1 U24.6 U24.24 U24.38 | length 45.6
  L1 - TOP w0.3: U24.24@107.3,49.75 v1(108.15,49.75) ; U24.38@110.45,45.1 v1(110.45,45.95) ; U24.6@112.95,53.9 112.95,53.15 v1(113,53.1)
  L5 - VCC w0.3: 115.9,50.125 115.9,50.225 ; v1(122.5,49.1) 121.6,50 119,50 118.45,50.55 117.45,50.55 117.15,50.25 115.925,50.25 115.9,50.225 ; 115.9,50.225 115.9,46.439 115.011,45.55 110.85,45.55 v1(110.45,45.95) 108.65,45.95 107.964,46.636 107.964,47.3 107.7,47.564 107.7,47.936 107.964,48.2 108.15,48.386 v1(108.15,49.75) 108.15,52.45 109.375,53.675 112.4,53.675 113,53.075 v1(113,53.1) 114.85,53.1 115.9,52.05 115.9,50.225
  L6 - BOT w0.3: C238.2@107.35,48.9 107.35,49.05 108.05,49.75 v1(108.15,49.75) ; v1(110.45,45.95) 110.45,45.55 110.789,45.211 110.789,45.15 C237.2@111.2,45.15 ; v1(113,53.1) 113,53.197 113.037,53.197 113.314,53.475 113.4,53.475 113.675,53.75 C239.2@113.7,53.75 ; v1(122.5,49.1) FB25.1@122.5,50
  L6 - BOT w0.5: FB25.1@122.5,50 C236.2@124.2,50
VDDFUSE: C9.2 C55.2 U2.19 U4.M12 | length 139.3
  L1 - TOP w0.2: U4.M12@66.4,47.6 v1(66.8,48)
  L1 - TOP w0.3: U2.19@29.5,78.25 30.75,78.25 31.307,78.25 31.457,78.4 C9.2@31.85,78.4
  L5 - VCC w0.2: v1(66.8,48) 67.2,47.6 67.8,47.6 68,47.4 68,46.8 68.8,46 69.4,46 69.6,45.8 69.6,45.2
  L5 - VCC w0.4: v1@30.8,78.1 31.95,78.1 32.75,78.9 34.025,78.9 36.725,81.6 52.5,81.6 60.5,73.6 89.1,73.6 97,65.7 97,41.4 94.4,38.8 82.2,38.8 80.7,37.3 77.5,37.3 69.6,45.2
  L6 - BOT w0.3: v1(66.8,48) 67.2,48.4 C55.2@67.338,48.4
  other v1: 30.8,78.2
VDDHSIC: C47.2 FB2.2 U4.R9 | length 13
  L1 - TOP w0.4: U4.R9@64,45.2 v1(64.4,44.8)
  L3 - SIG w0.3: v1(64.4,44.8) 64.4,42.864 64.719,42.545 64.719,40.571 v1(65.5,39.79)
  L4 - SIG w0.3: v1(64.4,44.8) 64.4,42.864 64.719,42.545 64.719,40.571 v1(65.5,39.79)
  L6 - BOT w0.3: v1(64.4,44.8) 64.8,44.4 C47.2@64.938,44.4
  L6 - BOT w0.4: FB2.2@65.5,39 v1(65.5,39.79)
